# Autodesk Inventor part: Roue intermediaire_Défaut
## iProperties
Shininess: 64.0
Length Units: 11269
Angle Units: 11279
Time Units: 11290
Mass Units: 11283
Length Display Precision: 3
Angle Display Precision: 2
Compacted: True
Part Number: Roue intermediaire_Défaut
Document SubType Name: Modeling
Created: 2006-01
Material: Par défaut
Designer: Fricot
Density: 0.0
Volumn: 0.0
Area: 0.0
PropertySet Name: Model Information
Control State: 0
Master: False
Checked Out: False
Author: Fricot
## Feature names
1. Base1
